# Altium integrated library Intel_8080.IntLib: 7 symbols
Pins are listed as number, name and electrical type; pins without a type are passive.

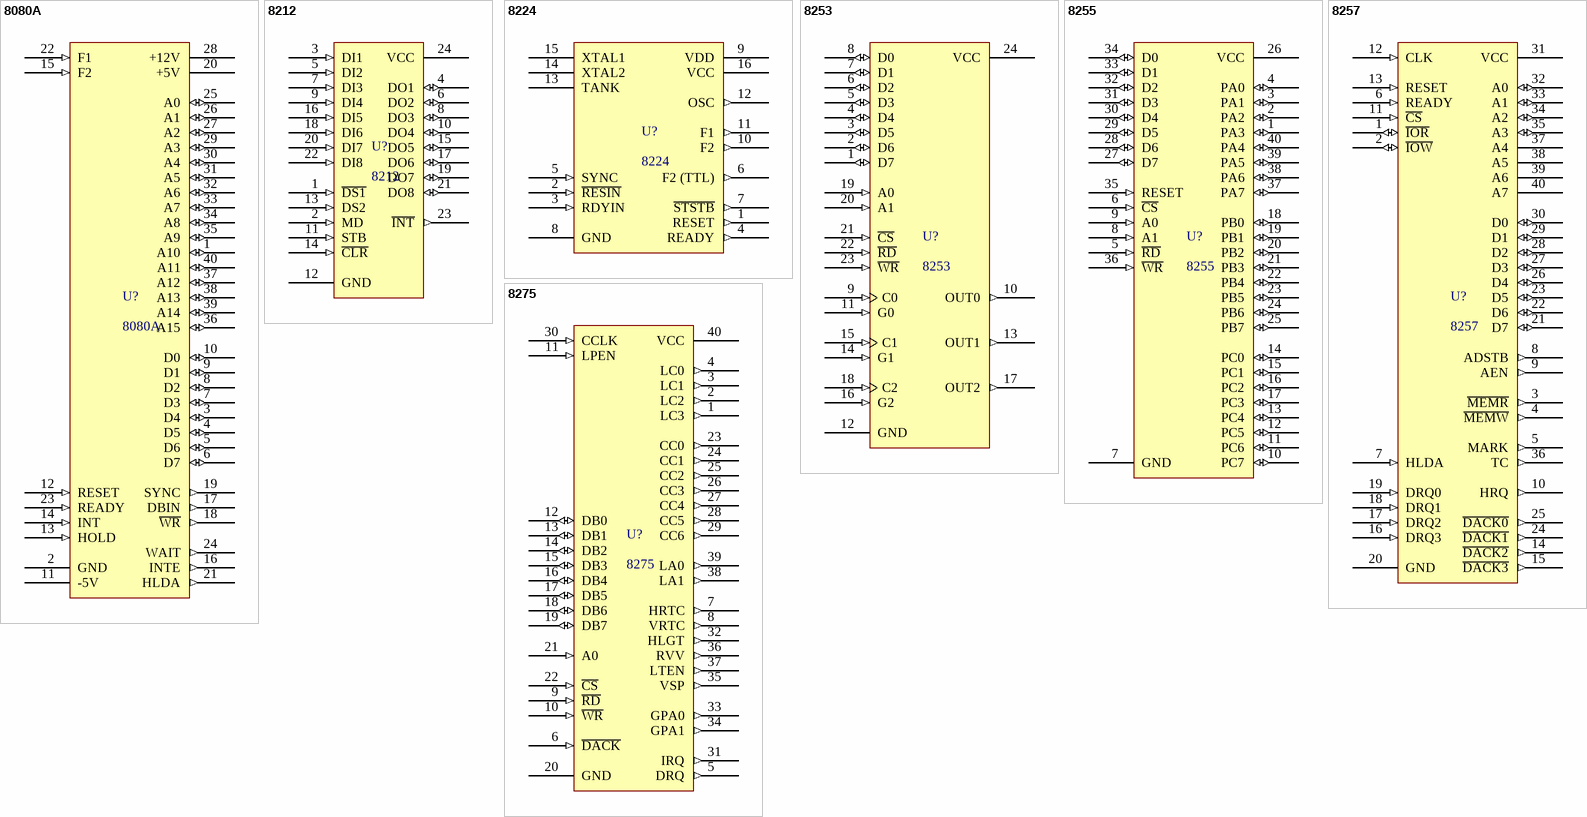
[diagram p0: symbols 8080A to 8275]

## 8080A
designator U?
8-bit N-channel microprocessor
footprint DIP40M (2.5mm grid)
pins: 1 A10 (io), 2 GND (power), 3 D4 (io), 4 D5 (io), 5 D6 (io), 6 D7 (io), 7 D3 (io), 8 D2 (io), 9 D1 (io), 10 D0 (io), 11 -5V (power), 12 RESET (in), 13 HOLD (in), 14 INT (in), 15 F2 (in), 16 INTE (out), 17 DBIN (out), 18 ~{WR} (out), 19 SYNC (out), 20 +5V (power), 21 HLDA (out), 22 F1 (in), 23 READY (in), 24 WAIT (out), 25 A0 (io), 26 A1 (io), 27 A2 (io), 28 +12V (power), 29 A3 (io), 30 A4 (io), 31 A5 (io), 32 A6 (io), 33 A7 (io), 34 A8 (io), 35 A9 (io), 36 A15 (io), 37 A12 (io), 38 A13 (io), 39 A14 (io), 40 A11 (io)

## 8212
designator U?
8-bit input/output port
footprint DIP24M (2.5mm grid, 239.24-1, 239.24-2, 239.24-6, 239.24-7)
pins: 1 ~{DS1} (in), 2 MD (in), 3 DI1 (in), 4 DO1 (io), 5 DI2 (in), 6 DO2 (io), 7 DI3 (in), 8 DO3 (io), 9 DI4 (in), 10 DO4 (io), 11 STB (in), 12 GND (power), 13 DS2 (in), 14 ~{CLR} (in), 15 DO5 (io), 16 DI5 (in), 17 DO6 (io), 18 DI6 (in), 19 DO7 (io), 20 DI7 (in), 21 DO8 (io), 22 DI8 (in), 23 ~{INT} (out), 24 VCC (power)

## 8224
designator U?
Clock generator and driver for 8080A CPU
footprint DIP16M (2.5mm grid)
pins: 1 RESET (out) "Reset Output", 2 ~{RESIN} (in) "Reset Input", 3 RDYIN (in) "Ready Input", 4 READY (out) "Ready Output", 5 SYNC (in) "Sync Input", 6 F2 (TTL) (out) "F2 CLK (TTL Level)", 7 ~{STSTB} (out) "Status STB (Active Low)", 8 GND (power) "0V", 9 VDD (power) "+12V", 10 F2 (out) "8080 Clock", 11 F1 (out) "8080 Clock", 12 OSC (out) "Oscillator Output", 13 TANK "Used with Overtone XTAL", 14 XTAL2 "Connection for Crystal", 15 XTAL1 "Connection for Crystal", 16 VCC (power) "+5V"

## 8253
designator U?
Programmable interval timer
footprint DIP24M (2.5mm grid, 239.24-1, 239.24-2, 239.24-6, 239.24-7)
pins: 1 D7 (io), 2 D6 (io), 3 D5 (io), 4 D4 (io), 5 D3 (io), 6 D2 (io), 7 D1 (io), 8 D0 (io), 9 C0 (in), 10 OUT0 (out), 11 G0 (in), 12 GND (power), 13 OUT1 (out), 14 G1 (in), 15 C1 (in), 16 G2 (in), 17 OUT2 (out), 18 C2 (in), 19 A0 (in), 20 A1 (in), 21 ~{CS} (in), 22 ~{RD} (in), 23 ~{WR} (in), 24 VCC (power)

## 8255
designator U?
Programmable peripheral interface
footprint DIP40M (2.5mm grid)
pins: 1 PA3 (io), 2 PA2 (io), 3 PA1 (io), 4 PA0 (io), 5 ~{RD} (in), 6 ~{CS} (in), 7 GND (power), 8 A1 (in), 9 A0 (in), 10 PC7 (io), 11 PC6 (io), 12 PC5 (io), 13 PC4 (io), 14 PC0 (io), 15 PC1 (io), 16 PC2 (io), 17 PC3 (io), 18 PB0 (io), 19 PB1 (io), 20 PB2 (io), 21 PB3 (io), 22 PB4 (io), 23 PB5 (io), 24 PB6 (io), 25 PB7 (io), 26 VCC (power), 27 D7 (io), 28 D6 (io), 29 D5 (io), 30 D4 (io), 31 D3 (io), 32 D2 (io), 33 D1 (io), 34 D0 (io), 35 RESET (in), 36 ~{WR} (in), 37 PA7 (io), 38 PA6 (io), 39 PA5 (io), 40 PA4 (io)

## 8257
designator U?
Programmable DMA controller
footprint DIP40M (2.5mm grid)
pins: 1 ~{IOR} (io), 2 ~{IOW} (io), 3 ~{MEMR} (out), 4 ~{MEMW} (out), 5 MARK (out), 6 READY (in), 7 HLDA (in), 8 ADSTB (out), 9 AEN (out), 10 HRQ (out), 11 ~{CS} (in), 12 CLK (in), 13 RESET (in), 14 ~{DACK2} (out), 15 ~{DACK3} (out), 16 DRQ3 (in), 17 DRQ2 (in), 18 DRQ1 (in), 19 DRQ0 (in), 20 GND (power), 21 D7 (io), 22 D6 (io), 23 D5 (io), 24 ~{DACK1} (out), 25 ~{DACK0} (out), 26 D4 (io), 27 D3 (io), 28 D2 (io), 29 D1 (io), 30 D0 (io), 31 VCC (power), 32 A0 (io), 33 A1 (io), 34 A2 (io), 35 A3 (io), 36 TC (out), 37 A4, 38 A5, 39 A6, 40 A7

## 8275
designator U?
Programmable CRT controller
footprint DIP40M (2.5mm grid, 2123.40-1)
pins: 1 LC3 (out), 2 LC2 (out), 3 LC1 (out), 4 LC0 (out), 5 DRQ (out), 6 ~{DACK} (in), 7 HRTC (out), 8 VRTC (out), 9 ~{RD} (in), 10 ~{WR} (in), 11 LPEN (in), 12 DB0 (io), 13 DB1 (io), 14 DB2 (io), 15 DB3 (io), 16 DB4 (io), 17 DB5 (io), 18 DB6 (io), 19 DB7 (io), 20 GND (power), 21 A0 (in), 22 ~{CS} (in), 23 CC0 (out), 24 CC1 (out), 25 CC2 (out), 26 CC3 (out), 27 CC4 (out), 28 CC5 (out), 29 CC6 (out), 30 CCLK (in), 31 IRQ (out), 32 HLGT (out), 33 GPA0 (out), 34 GPA1 (out), 35 VSP (out), 36 RVV (out), 37 LTEN (out), 38 LA1 (out), 39 LA0 (out), 40 VCC (power)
